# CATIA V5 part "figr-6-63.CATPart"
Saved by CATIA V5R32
Part number: Part1
Bounding box of the stored display mesh (mm): x -50.648 to 50.648, y -72.183 to 72.183, z -40 to 40
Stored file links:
  D:\PROJECTS\Project 2022\CATIA V5 6R 2022\Resources\Part Files\c06_catia_v5_6r2022_prt\figr-6-63.CATPart
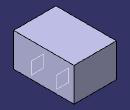
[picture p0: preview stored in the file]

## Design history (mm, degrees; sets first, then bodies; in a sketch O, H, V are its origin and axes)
Set1
  Plane1: type Offset, RefPlane face of Pad1, Offset -50, reversed
  Plane2: type Offset, RefPlane Plane1, Offset 53
Body1 (main body)
  Sketch1 on xy-plane, origin (0, 0, 0), H (1, 0, 0), V (0, 1, 0)
    line L1 (-50.6478, 72.1832) -> (50.6478, 72.1832)
    line L2 (50.6478, 72.1832) -> (50.6478, -72.1832)
    line L3 (50.6478, -72.1832) -> (-50.6478, -72.1832)
    line L4 (-50.6478, -72.1832) -> (-50.6478, 72.1832)
    axis line L5 (50.6478, -72.1832) -> (-50.6478, 72.1832)
    horizontal: L1 H, L3 H
    vertical: L2 V, L4 V
    midpoint: O L5
  Pad1: profile Sketch1, direction (0, 0, 1), length 40, mirrored extent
